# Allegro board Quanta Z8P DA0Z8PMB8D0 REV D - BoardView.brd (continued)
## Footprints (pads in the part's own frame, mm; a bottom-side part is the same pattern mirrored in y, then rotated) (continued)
C0402
  custom 0.12x0.12 smd: 1(0.39,0) 2(-0.39,0)
C0402_2
  custom 0.12x0.12 smd: 1(0.39,0) 2(-0.39,0)
C0603
  rect 0.686x0.813 smd: 1(0.6,0) 2(-0.6,0)
C0805
  rect 0.864x1.372 smd: 1(0.88,0) 2(-0.88,0)
C1206
  rect 1.219x1.626 smd: 1(1.4,0) 2(-1.4,0)
CC1808
  rect 2.159x2.286 smd: 1(-2.349,0) 2(2.349,0)
CC7343
  rect 2.413x2.819 smd: 1(-3.2,0) 2(3.2,0)
CHOKE-PCMC063T-3R3MN-SMT
  rect 1.854x3.505 smd: 1(-3.275,0) 2(3.275,0)
D-2_8X1_78
  rect 2.21x1.397 smd: 1(-0.95,0)
  rect 0.889x1.397 smd: 2(1.6,0)
D-3_8X2_5
  rect 1.6x1.905 smd: 1(-2.15,0) 2(2.15,0)
D-TO277_213-6_1X4_3
  rect 1.168x1.397 smd: 1(3.885,1.05) 2(3.885,-1.05)
  rect 4.648x3.505 smd: 3(0,0)
DFN8-2X2-5-9P-ISL6208BCRZ
  rect 0.229x0.508 smd: 1(-0.75,-0.95) 2(-0.25,-0.95) 3(0.25,-0.95) 4(0.75,-0.95) 5(0.75,0.95) 6(0.25,0.95) 7(-0.25,0.95) 8(-0.75,0.95)
  rect 1.549x0.889 smd: 9(0,0)
DFN10-3X3-5-11P-G5318
  rect 0.254x0.711 smd: 1(-1,-1.5) 2(-0.5,-1.5) 3(0,-1.5) 4(0.5,-1.5) 5(1,-1.5) 6(1,1.5) 7(0.5,1.5) 8(0,1.5) 9(-0.5,1.5) 10(-1,1.5)
  rect 2.591x1.6 smd: 11(0,0)
DFN10-4_1X2-8-11P
  rect 0.203x0.61 smd: 1(-1.8,-0.9) 2(-1,-0.9) 3(-0.2,-0.9) 4(0.6,-0.9) 5(1.4,-0.9) 6(1.8,0.9) 7(1,0.9) 8(0.2,0.9) 9(-0.6,0.9) 10(-1.4,0.9)
  rect 1.397x0.787 smd: 11(-0.4,0)
DFN-8L-3X3-65-5P-0_9H
  rect 0.508x0.356 smd: 1(1.4,-0.975) 2(1.4,-0.325) 3(1.4,0.325) 4(1.4,0.975)
  custom 0.57x0.57 smd: 5(-0.51,0)
DSM
  rect 1.016x0.508 smd: 1(-1.3,0) 2(1.321,0)
ECAP6_3X6_1-7_2
  rect 3.505x1.6 smd: 1(2.8,0) 2(-2.8,0)
ESD-1X0_6-2P
  rect 0.559x0.61 smd: 1(-0.425,0) 2(0.425,0)
ESD-3_8X1-9P
  rect 0.203x0.61 smd: 1(-1.7,-0.475) 2(-0.8,-0.475) 3(0,-0.475) 4(0.8,-0.475) 5(1.7,-0.475) 6(1.3,0.475) 7(0.4,0.475) 8(-0.4,0.475) 9(-1.3,0.475)
FBGA169-SAMSUNG-KMHOG0000M-0_5S
  round 0.254 smd: A4(-6.75,-1.75) A6(-6.75,-0.75) A9(-6.75,0.75) A11(-6.75,1.75) AA1(3.25,-3.25) AA2(3.25,-2.75) AA3(3.25,-2.25) AA4(3.25,-1.75) AA5(3.25,-1.25) AA6(3.25,-0.75) AA7(3.25,-0.25) AA8(3.25,0.25) AA9(3.25,0.75) AA10(3.25,1.25) AA11(3.25,1.75) AA12(3.25,2.25) AA13(3.25,2.75) AA14(3.25,3.25) AE1(5.25,-3.25) AE14(5.25,3.25) AG2(6.25,-2.75) AG13(6.25,2.75) AH4(6.75,-1.75) AH6(6.75,-0.75) AH9(6.75,0.75) AH11(6.75,1.75) B2(-6.25,-2.75) B13(-6.25,2.75) D1(-5.25,-3.25) D14(-5.25,3.25) H1(-3.25,-3.25) H2(-3.25,-2.75) H3(-3.25,-2.25) H4(-3.25,-1.75) H5(-3.25,-1.25) H6(-3.25,-0.75) H7(-3.25,-0.25) H8(-3.25,0.25) H9(-3.25,0.75) H10(-3.25,1.25) H11(-3.25,1.75) H12(-3.25,2.25) H13(-3.25,2.75) H14(-3.25,3.25) J1(-2.75,-3.25) J2(-2.75,-2.75) J3(-2.75,-2.25) J4(-2.75,-1.75) J5(-2.75,-1.25) J6(-2.75,-0.75) J7(-2.75,-0.25) J8(-2.75,0.25) J9(-2.75,0.75) J10(-2.75,1.25) J11(-2.75,1.75) J12(-2.75,2.25) J13(-2.75,2.75) J14(-2.75,3.25) K1(-2.25,-3.25) K2(-2.25,-2.75) K3(-2.25,-2.25) K4(-2.25,-1.75) K5(-2.25,-1.25) K6(-2.25,-0.75) K7(-2.25,-0.25) K8(-2.25,0.25) K9(-2.25,0.75) K10(-2.25,1.25) K11(-2.25,1.75) K12(-2.25,2.25) K13(-2.25,2.75) K14(-2.25,3.25) L1(-1.75,-3.25) L2(-1.75,-2.75) L3(-1.75,-2.25) L4(-1.75,-1.75) L12(-1.75,2.25) L13(-1.75,2.75) L14(-1.75,3.25) M1(-1.25,-3.25) M2(-1.25,-2.75) M3(-1.25,-2.25) M5(-1.25,-1.25) M6(-1.25,-0.75) M7(-1.25,-0.25) M8(-1.25,0.25) M9(-1.25,0.75) M10(-1.25,1.25) M12(-1.25,2.25) M13(-1.25,2.75) M14(-1.25,3.25) N1(-0.75,-3.25) N2(-0.75,-2.75) N3(-0.75,-2.25) N5(-0.75,-1.25) N10(-0.75,1.25) N12(-0.75,2.25) N13(-0.75,2.75) N14(-0.75,3.25) P1(-0.25,-3.25) P2(-0.25,-2.75) P3(-0.25,-2.25) P5(-0.25,-1.25) P10(-0.25,1.25) P12(-0.25,2.25) P13(-0.25,2.75) P14(-0.25,3.25) R1(0.25,-3.25) R2(0.25,-2.75) R3(0.25,-2.25) R5(0.25,-1.25) R10(0.25,1.25) R12(0.25,2.25) R13(0.25,2.75) R14(0.25,3.25) T1(0.75,-3.25) T2(0.75,-2.75) T3(0.75,-2.25) T5(0.75,-1.25) T10(0.75,1.25) T12(0.75,2.25) T13(0.75,2.75) T14(0.75,3.25) U1(1.25,-3.25) U2(1.25,-2.75) U3(1.25,-2.25) U5(1.25,-1.25) U6(1.25,-0.75) U7(1.25,-0.25) U8(1.25,0.25) U9(1.25,0.75) U10(1.25,1.25) U12(1.25,2.25) U13(1.25,2.75) U14(1.25,3.25) V1(1.75,-3.25) V2(1.75,-2.75) V3(1.75,-2.25) V12(1.75,2.25) V13(1.75,2.75) V14(1.75,3.25) W1(2.25,-3.25) W2(2.25,-2.75) W3(2.25,-2.25) W4(2.25,-1.75) W5(2.25,-1.25) W6(2.25,-0.75) W7(2.25,-0.25) W8(2.25,0.25) W9(2.25,0.75) W10(2.25,1.25) W11(2.25,1.75) W12(2.25,2.25) W13(2.25,2.75) W14(2.25,3.25) Y1(2.75,-3.25) Y2(2.75,-2.75) Y3(2.75,-2.25) Y4(2.75,-1.75) Y5(2.75,-1.25) Y6(2.75,-0.75) Y7(2.75,-0.25) Y8(2.75,0.25) Y9(2.75,0.75) Y10(2.75,1.25) Y11(2.75,1.75) Y12(2.75,2.25) Y13(2.75,2.75) Y14(2.75,3.25)
FILTER-MCM2012B900GBE-4P
  rect 0.762x0.406 smd: 1(-0.925,0.4) 2(0.925,0.4) 3(0.925,-0.4) 4(-0.925,-0.4)
GS12201-1011-9H-20P-L
  round 0.838 hole 0.838 unplated: (-5.8,0) (5.8,0)
  rect 0.254x1.143 smd: 1(-4.75,2.325) 2(-4.25,2.325) 3(-3.75,2.325) 4(-3.25,2.325) 5(-2.75,2.325) 6(-2.25,2.325) 7(-1.75,2.325) 8(-1.25,2.325) 9(-0.75,2.325) 10(-0.25,2.325) 11(0.25,2.325) 12(0.75,2.325) 13(1.25,2.325) 14(1.75,2.325) 15(2.25,2.325) 16(2.75,2.325) 17(3.25,2.325) 18(3.75,2.325) 19(4.25,2.325) 20(4.75,2.325)
  rect 1.295x1.397 smd: 21(-5.8,2.2) 22(5.8,2.2) 23(-5.8,-1.8) 24(5.8,-1.8)
H-C122D122N
  round 3.099 hole 3.099 unplated: (0,0)
H-C236D94P2
  round 5.994 hole 2.388: 1(0,0)
H-C236D126P2
  round 5.994 hole 3.2: 1(0,0)
H-TC252IC138BC252D138P2
  round 6.401 hole 3.505: 1(0,0)
HDMI-HMRBL-AK120C-19P
  round 0.787 hole 0.559: 1(-4.5,8.15) 2(-4,9.7) 3(-3.5,8.15) 4(-3,9.7) 5(-2.5,8.15) 6(-2,9.7) 7(-1.5,8.15) 8(-1,9.7) 9(-0.5,8.15) 10(0,9.7) 11(0.5,8.15) 12(1,9.7) 13(1.5,8.15) 14(2,9.7) 15(2.5,8.15) 16(3,9.7) 17(3.5,8.15) 18(4,9.7) 19(4.5,8.15)
  oval 1.397x2.108 hole 0.787x1.499: 20(-7.25,8.35) 21(7.25,8.35)
  oval 1.702x2.896 hole 1.092x2.311: 22(-8.75,0) 23(8.75,0)
HG-C315D165P2
  round 8.001 hole 4.191: 1(0,0)
  round 1.016 hole 0.61: 2(0,3.048) 3(2.155,2.155) 4(3.048,0) 5(2.155,-2.155) 6(0,-3.048) 7(-2.155,-2.155) 8(-3.048,0) 9(-2.155,2.155)
HG-C354D126P2
  round 8.992 hole 3.2: 1(0,0)
  round 1.016 hole 0.61: 2(0,3.048) 3(2.155,2.155) 4(3.048,0) 5(2.155,-2.155) 6(0,-3.048) 7(-2.155,-2.155) 8(-3.048,0) 9(-2.155,2.155)
HG-C354D220P2
  round 8.992 hole 5.588: 1(0,0)
  round 1.016 hole 0.61: 2(0,3.556) 3(2.514,2.514) 4(3.556,0) 5(2.514,-2.514) 6(0,-3.556) 7(-2.514,-2.514) 8(-3.556,0) 9(-2.514,2.514)
HG-EJ-AP-1
  custom 2.25x2.25 hole 3.2: 1(0,0)
  round 1.016 hole 0.61: 2(0,2.667) 3(1.886,1.886) 4(2.667,0) 5(1.886,-1.886) 6(0,-2.667) 7(-1.886,-1.886) 8(-2.667,0) 9(-1.886,1.886)
HG-TC315BC236D95P2
  round 8.001 hole 2.413: 1(0,0)
  round 1.016 hole 0.61: 2(0,2.032) 3(1.437,1.437) 4(2.032,0) 5(1.437,-1.437) 6(0,-2.032) 7(-1.437,-1.437) 8(-2.032,0) 9(-1.437,1.437)
HG-Z8P-1
  custom 2.25x2.25 hole 3.2: 1(0,0)
  round 1.016 hole 0.61: 2(0,3.048) 3(2.155,2.155) 4(3.048,0) 5(2.155,-2.155) 6(0,-3.048) 7(-2.155,-2.155) 8(-3.048,0) 9(-2.155,2.155)
JOPEN25X30_S
  custom 0.159x0.159 smd: 1(-0.368,0) 2(0.368,0)
L2_5X2-1_2H
  rect 0.889x2.108 smd: 1(-0.85,0) 2(0.85,0)
L3_2X2_5-1_55
  rect 1.245x2.007 smd: 1(-1.275,0) 2(1.275,0)
L5_1X5_2-1_6H
  rect 1.905x2.489 smd: 1(-2.047,0) 2(2.047,0)
L6_6X6_6-3_8
  rect 2.362x3.505 smd: 1(-3.025,0) 2(3.025,0)
LGA16-3X3-5
  rect 0.305x0.94 smd: 1(-1,-1.525) 2(-0.5,-1.525) 3(0,-1.525) 4(0.5,-1.525) 5(1,-1.525) 9(1,1.525) 10(0.5,1.525) 11(0,1.525) 12(-0.5,1.525) 13(-1,1.525)
  rect 0.94x0.305 smd: 6(1.525,-0.5) 7(1.525,0) 8(1.525,0.5) 14(-1.525,0.5) 15(-1.525,0) 16(-1.525,-0.5)
LQFP128-16X16-4-1_6H
  rect 0.203x1.499 smd: 1(-6.2,-7.85) 2(-5.8,-7.85) 3(-5.4,-7.85) 4(-5,-7.85) 5(-4.6,-7.85) 6(-4.2,-7.85) 7(-3.8,-7.85) 8(-3.4,-7.85) 9(-3,-7.85) 10(-2.6,-7.85) 11(-2.2,-7.85) 12(-1.8,-7.85) 13(-1.4,-7.85) 14(-1,-7.85) 15(-0.6,-7.85) 16(-0.2,-7.85) 17(0.2,-7.85) 18(0.6,-7.85) 19(1,-7.85) 20(1.4,-7.85) 21(1.8,-7.85) 22(2.2,-7.85) 23(2.6,-7.85) 24(3,-7.85) 25(3.4,-7.85) 26(3.8,-7.85) 27(4.2,-7.85) 28(4.6,-7.85) 29(5,-7.85) 30(5.4,-7.85) 31(5.8,-7.85) 32(6.2,-7.85) 65(6.2,7.85) 66(5.8,7.85) 67(5.4,7.85) 68(5,7.85) 69(4.6,7.85) 70(4.2,7.85) 71(3.8,7.85) 72(3.4,7.85) 73(3,7.85) 74(2.6,7.85) 75(2.2,7.85) 76(1.8,7.85) 77(1.4,7.85) 78(1,7.85) 79(0.6,7.85) 80(0.2,7.85) 81(-0.2,7.85) 82(-0.6,7.85) 83(-1,7.85) 84(-1.4,7.85) 85(-1.8,7.85) 86(-2.2,7.85) 87(-2.6,7.85) 88(-3,7.85) 89(-3.4,7.85) 90(-3.8,7.85) 91(-4.2,7.85) 92(-4.6,7.85) 93(-5,7.85) 94(-5.4,7.85) 95(-5.8,7.85) 96(-6.2,7.85)
  rect 1.499x0.203 smd: 33(7.85,-6.2) 34(7.85,-5.8) 35(7.85,-5.4) 36(7.85,-5) 37(7.85,-4.6) 38(7.85,-4.2) 39(7.85,-3.8) 40(7.85,-3.4) 41(7.85,-3) 42(7.85,-2.6) 43(7.85,-2.2) 44(7.85,-1.8) 45(7.85,-1.4) 46(7.85,-1) 47(7.85,-0.6) 48(7.85,-0.2) 49(7.85,0.2) 50(7.85,0.6) 51(7.85,1) 52(7.85,1.4) 53(7.85,1.8) 54(7.85,2.2) 55(7.85,2.6) 56(7.85,3) 57(7.85,3.4) 58(7.85,3.8) 59(7.85,4.2) 60(7.85,4.6) 61(7.85,5) 62(7.85,5.4) 63(7.85,5.8) 64(7.85,6.2) 97(-7.85,6.2) 98(-7.85,5.8) 99(-7.85,5.4) 100(-7.85,5) 101(-7.85,4.6) 102(-7.85,4.2) 103(-7.85,3.8) 104(-7.85,3.4) 105(-7.85,3) 106(-7.85,2.6) 107(-7.85,2.2) 108(-7.85,1.8) 109(-7.85,1.4) 110(-7.85,1) 111(-7.85,0.6) 112(-7.85,0.2) 113(-7.85,-0.2) 114(-7.85,-0.6) 115(-7.85,-1) 116(-7.85,-1.4) 117(-7.85,-1.8) 118(-7.85,-2.2) 119(-7.85,-2.6) 120(-7.85,-3) 121(-7.85,-3.4) 122(-7.85,-3.8) 123(-7.85,-4.2) 124(-7.85,-4.6) 125(-7.85,-5) 126(-7.85,-5.4) 127(-7.85,-5.8) 128(-7.85,-6.2)
ML1220-SMT
  round 0.711 hole 0.711 unplated: (0,-3.988)
  round 1.092 hole 1.092 unplated: (0,3.988)
  rect 2.997x1.499 smd: 1(-7.391,0) 2(7.391,0)
NGFF-APCI0076-P001A-75P-KE-SMT
  round 1.194 hole 1.194 unplated: (-10,0)
  round 1.702 hole 1.702 unplated: (10,0)
  rect 0.279x1.549 smd: 1(-9.25,5.275) 2(-9,-2.275) 3(-8.75,5.275) 4(-8.5,-2.275) 5(-8.25,5.275) 6(-8,-2.275) 7(-7.75,5.275) 8(-7.5,-2.275) 9(-7.25,5.275) 10(-7,-2.275) 11(-6.75,5.275) 12(-6.5,-2.275) 13(-6.25,5.275) 14(-6,-2.275) 15(-5.75,5.275) 16(-5.5,-2.275) 17(-5.25,5.275) 18(-5,-2.275) 19(-4.75,5.275) 20(-4.5,-2.275) 21(-4.25,5.275) 22(-4,-2.275) 23(-3.75,5.275) 32(-1.5,-2.275) 33(-1.25,5.275) 34(-1,-2.275) 35(-0.75,5.275) 36(-0.5,-2.275) 37(-0.25,5.275) 38(0,-2.275) 39(0.25,5.275) 40(0.5,-2.275) 41(0.75,5.275) 42(1,-2.275) 43(1.25,5.275) 44(1.5,-2.275) 45(1.75,5.275) 46(2,-2.275) 47(2.25,5.275) 48(2.5,-2.275) 49(2.75,5.275) 50(3,-2.275) 51(3.25,5.275) 52(3.5,-2.275) 53(3.75,5.275) 54(4,-2.275) 55(4.25,5.275) 56(4.5,-2.275) 57(4.75,5.275) 58(5,-2.275) 59(5.25,5.275) 60(5.5,-2.275) 61(5.75,5.275) 62(6,-2.275) 63(6.25,5.275) 64(6.5,-2.275) 65(6.75,5.275) 66(7,-2.275) 67(7.25,5.275) 68(7.5,-2.275) 69(7.75,5.275) 70(8,-2.275) 71(8.25,5.275) 72(8.5,-2.275) 73(8.75,5.275) 74(9,-2.275) 75(9.25,5.275)
  rect 1.194x2.743 smd: 76(-10.35,4.5) 77(10.35,4.5)
NGFF-NASM0-S6701-TS40-75P-KM
  round 1.194 hole 1.194 unplated: (-10,0)
  round 1.702 hole 1.702 unplated: (10,0)
  rect 0.279x1.549 smd: 1(-9.25,5.275) 2(-9,-2.275) 3(-8.75,5.275) 4(-8.5,-2.275) 5(-8.25,5.275) 6(-8,-2.275) 7(-7.75,5.275) 8(-7.5,-2.275) 9(-7.25,5.275) 10(-7,-2.275) 11(-6.75,5.275) 12(-6.5,-2.275) 13(-6.25,5.275) 14(-6,-2.275) 15(-5.75,5.275) 16(-5.5,-2.275) 17(-5.25,5.275) 18(-5,-2.275) 19(-4.75,5.275) 20(-4.5,-2.275) 21(-4.25,5.275) 22(-4,-2.275) 23(-3.75,5.275) 24(-3.5,-2.275) 25(-3.25,5.275) 26(-3,-2.275) 27(-2.75,5.275) 28(-2.5,-2.275) 29(-2.25,5.275) 30(-2,-2.275) 31(-1.75,5.275) 32(-1.5,-2.275) 33(-1.25,5.275) 34(-1,-2.275) 35(-0.75,5.275) 36(-0.5,-2.275) 37(-0.25,5.275) 38(0,-2.275) 39(0.25,5.275) 40(0.5,-2.275) 41(0.75,5.275) 42(1,-2.275) 43(1.25,5.275) 44(1.5,-2.275) 45(1.75,5.275) 46(2,-2.275) 47(2.25,5.275) 48(2.5,-2.275) 49(2.75,5.275) 50(3,-2.275) 51(3.25,5.275) 52(3.5,-2.275) 53(3.75,5.275) 54(4,-2.275) 55(4.25,5.275) 56(4.5,-2.275) 57(4.75,5.275) 58(5,-2.275) 67(7.25,5.275) 68(7.5,-2.275) 69(7.75,5.275) 70(8,-2.275) 71(8.25,5.275) 72(8.5,-2.275) 73(8.75,5.275) 74(9,-2.275) 75(9.25,5.275)
  rect 1.194x2.743 smd: 76(-10.35,4.5) 77(10.35,4.5)
O-EJ-KBL-1
  round 3.962 hole 3.962 unplated: (0,0)
POWER-3_3X3_3-65-5P-SMT
  rect 0.762x0.432 smd: 1(1.43,-0.975) 2(1.43,-0.325) 3(1.43,0.325) 4(1.43,0.975)
  custom 0.562x0.562 smd: 5(-0.725,0)
POWER-5_2X5_55-1_27-5P
  rect 0.66x0.508 smd: 1(2.755,-1.905) 2(2.755,-0.635) 3(2.755,0.635) 4(2.755,1.905)
  custom 1.15x1.15 smd: 5(0,0)
POWER-5X5-1_27-5P
  rect 1.143x0.762 smd: 1(2.875,-1.905) 2(2.875,-0.635) 3(2.875,0.635) 4(2.875,1.905)
  custom 1.14x1.14 smd: 5(0,0)
PVQFN20-3_5X3_5-5-25P
  rect 0.279x0.838 smd: 1(-1,-1.725) 2(-0.5,-1.725) 3(0,-1.725) 4(0.5,-1.725) 5(1,-1.725) 11(1,1.725) 12(0.5,1.725) 13(0,1.725) 14(-0.5,1.725) 15(-1,1.725)
  rect 0.838x0.279 smd: 6(1.725,-1) 7(1.725,-0.5) 8(1.725,0) 9(1.725,0.5) 10(1.725,1) 16(-1.725,1) 17(-1.725,0.5) 18(-1.725,0) 19(-1.725,-0.5) 20(-1.725,-1)
  rect 2.057x2.057 smd: 21(0,0)
  round 0.61 hole 0.305: 22(-0.5,-0.5) 23(0.5,-0.5) 24(0.5,0.5) 25(-0.5,0.5)
PWQFN20-4X4-5-26P-0_8H
  rect 0.279x0.991 smd: 1(-1,-1.9) 2(-0.5,-1.9) 3(0,-1.9) 4(0.5,-1.9) 5(1,-1.9) 11(1,1.9) 12(0.5,1.9) 13(0,1.9) 14(-0.5,1.9) 15(-1,1.9)
  rect 0.991x0.279 smd: 6(1.9,-1) 7(1.9,-0.5) 8(1.9,0) 9(1.9,0.5) 10(1.9,1) 16(-1.9,1) 17(-1.9,0.5) 18(-1.9,0) 19(-1.9,-0.5) 20(-1.9,-1)
  rect 2.159x2.159 smd: 21(0,0)
  round 0.61 hole 0.305: 22(-0.75,-0.75) 23(0.75,-0.75) 24(0.75,0.75) 25(-0.75,0.75) 26(0,0)
QFN10-3X3-5-16P
  rect 0.279x0.838 smd: 1(-1,-1.475) 2(-0.5,-1.475) 3(0,-1.475) 4(0.5,-1.475) 5(1,-1.475) 6(1,1.475) 7(0.5,1.475) 8(0,1.475) 9(-0.5,1.475) 10(-1,1.475)
  custom 0.413x0.413 smd: 11(0,0)
  round 0.508 hole 0.254: 12(-0.75,0.5) 13(0.75,0.5) 14(-0.75,-0.5) 15(0.75,-0.5) 16(0,0)
QFN20-3X3-45-21P
  custom 0.062x0.062 smd: 1(-0.9,-1.375) 5(0.9,-1.375) 6(1.375,-0.9) 10(1.375,0.9) 11(0.9,1.375) 15(-0.9,1.375) 16(-1.375,0.9) 20(-1.375,-0.9)
  rect 0.254x0.66 smd: 2(-0.45,-1.375) 3(0,-1.375) 4(0.45,-1.375) 12(0.45,1.375) 13(0,1.375) 14(-0.45,1.375)
  rect 0.66x0.254 smd: 7(1.375,-0.45) 8(1.375,0) 9(1.375,0.45) 17(-1.375,0.45) 18(-1.375,0) 19(-1.375,-0.45)
  rect 1.295x1.295 smd: 21(0,0)
QFN20-4X3-5-21P
  rect 0.254x0.991 smd: 1(-1.25,-1.6) 2(-0.75,-1.6) 3(-0.25,-1.6) 4(0.25,-1.6) 5(0.75,-1.6) 6(1.25,-1.6) 11(1.25,1.6) 12(0.75,1.6) 13(0.25,1.6) 14(-0.25,1.6) 15(-0.75,1.6) 16(-1.25,1.6)
  rect 0.991x0.254 smd: 7(2.1,-0.75) 8(2.1,-0.25) 9(2.1,0.25) 10(2.1,0.75) 17(-2.1,0.75) 18(-2.1,0.25) 19(-2.1,-0.25) 20(-2.1,-0.75)
  rect 2.591x1.6 smd: 21(0,0)
QFN32-5X5-5-33P-0_85H
  rect 0.305x0.991 smd: 1(-1.75,-2.6) 2(-1.25,-2.6) 3(-0.75,-2.6) 4(-0.25,-2.6) 5(0.25,-2.6) 6(0.75,-2.6) 7(1.25,-2.6) 8(1.75,-2.6) 17(1.75,2.6) 18(1.25,2.6) 19(0.75,2.6) 20(0.25,2.6) 21(-0.25,2.6) 22(-0.75,2.6) 23(-1.25,2.6) 24(-1.75,2.6)
  rect 0.991x0.305 smd: 9(2.6,-1.75) 10(2.6,-1.25) 11(2.6,-0.75) 12(2.6,-0.25) 13(2.6,0.25) 14(2.6,0.75) 15(2.6,1.25) 16(2.6,1.75) 25(-2.6,1.75) 26(-2.6,1.25) 27(-2.6,0.75) 28(-2.6,0.25) 29(-2.6,-0.25) 30(-2.6,-0.75) 31(-2.6,-1.25) 32(-2.6,-1.75)
  rect 3.505x3.505 smd: 33(0,0)
QFN32-5X5-5-37P-0_85H
  rect 0.279x0.838 smd: 1(-1.75,-2.55) 2(-1.25,-2.55) 3(-0.75,-2.55) 4(-0.25,-2.55) 5(0.25,-2.55) 6(0.75,-2.55) 7(1.25,-2.55) 8(1.75,-2.55) 17(1.75,2.55) 18(1.25,2.55) 19(0.75,2.55) 20(0.25,2.55) 21(-0.25,2.55) 22(-0.75,2.55) 23(-1.25,2.55) 24(-1.75,2.55)
  rect 0.838x0.279 smd: 9(2.55,-1.75) 10(2.55,-1.25) 11(2.55,-0.75) 12(2.55,-0.25) 13(2.55,0.25) 14(2.55,0.75) 15(2.55,1.25) 16(2.55,1.75) 25(-2.55,1.75) 26(-2.55,1.25) 27(-2.55,0.75) 28(-2.55,0.25) 29(-2.55,-0.25) 30(-2.55,-0.75) 31(-2.55,-1.25) 32(-2.55,-1.75)
  rect 3.759x3.759 smd: 33(0,0)
  round 0.508 hole 0.254: 34(-0.6,-0.6) 35(0.6,-0.6) 36(0.6,0.6) 37(-0.6,0.6)
QFN40-5X5-4-41P-ISL95859
  rect 0.203x0.61 smd: 1(-1.8,-2.4) 2(-1.4,-2.4) 3(-1,-2.4) 4(-0.6,-2.4) 5(-0.2,-2.4) 6(0.2,-2.4) 7(0.6,-2.4) 8(1,-2.4) 9(1.4,-2.4) 10(1.8,-2.4) 21(1.8,2.4) 22(1.4,2.4) 23(1,2.4) 24(0.6,2.4) 25(0.2,2.4) 26(-0.2,2.4) 27(-0.6,2.4) 28(-1,2.4) 29(-1.4,2.4) 30(-1.8,2.4)
  rect 0.61x0.203 smd: 11(2.4,-1.8) 12(2.4,-1.4) 13(2.4,-1) 14(2.4,-0.6) 15(2.4,-0.2) 16(2.4,0.2) 17(2.4,0.6) 18(2.4,1) 19(2.4,1.4) 20(2.4,1.8) 31(-2.4,1.8) 32(-2.4,1.4) 33(-2.4,1) 34(-2.4,0.6) 35(-2.4,0.2) 36(-2.4,-0.2) 37(-2.4,-0.6) 38(-2.4,-1) 39(-2.4,-1.4) 40(-2.4,-1.8)
  rect 3.505x3.505 smd: 41(0,0)
QFN48-6X6-4-49P-ALC280
  rect 0.203x0.991 smd: 1(-2.2,-3.1) 2(-1.8,-3.1) 3(-1.4,-3.1) 4(-1,-3.1) 5(-0.6,-3.1) 6(-0.2,-3.1) 7(0.2,-3.1) 8(0.6,-3.1) 9(1,-3.1) 10(1.4,-3.1) 11(1.8,-3.1) 12(2.2,-3.1) 25(2.2,3.1) 26(1.8,3.1) 27(1.4,3.1) 28(1,3.1) 29(0.6,3.1) 30(0.2,3.1) 31(-0.2,3.1) 32(-0.6,3.1) 33(-1,3.1) 34(-1.4,3.1) 35(-1.8,3.1) 36(-2.2,3.1)
  rect 0.991x0.203 smd: 13(3.1,-2.2) 14(3.1,-1.8) 15(3.1,-1.4) 16(3.1,-1) 17(3.1,-0.6) 18(3.1,-0.2) 19(3.1,0.2) 20(3.1,0.6) 21(3.1,1) 22(3.1,1.4) 23(3.1,1.8) 24(3.1,2.2) 37(-3.1,2.2) 38(-3.1,1.8) 39(-3.1,1.4) 40(-3.1,1) 41(-3.1,0.6) 42(-3.1,0.2) 43(-3.1,-0.2) 44(-3.1,-0.6) 45(-3.1,-1) 46(-3.1,-1.4) 47(-3.1,-1.8) 48(-3.1,-2.2)
  rect 4.394x4.394 smd: 49(0,0)
QFN48-6X6-4-49P-ASM1153
  rect 0.203x0.991 smd: 1(-2.2,-3.1) 2(-1.8,-3.1) 3(-1.4,-3.1) 4(-1,-3.1) 5(-0.6,-3.1) 6(-0.2,-3.1) 7(0.2,-3.1) 8(0.6,-3.1) 9(1,-3.1) 10(1.4,-3.1) 11(1.8,-3.1) 12(2.2,-3.1) 25(2.2,3.1) 26(1.8,3.1) 27(1.4,3.1) 28(1,3.1) 29(0.6,3.1) 30(0.2,3.1) 31(-0.2,3.1) 32(-0.6,3.1) 33(-1,3.1) 34(-1.4,3.1) 35(-1.8,3.1) 36(-2.2,3.1)
  rect 0.991x0.203 smd: 13(3.1,-2.2) 14(3.1,-1.8) 15(3.1,-1.4) 16(3.1,-1) 17(3.1,-0.6) 18(3.1,-0.2) 19(3.1,0.2) 20(3.1,0.6) 21(3.1,1) 22(3.1,1.4) 23(3.1,1.8) 24(3.1,2.2) 37(-3.1,2.2) 38(-3.1,1.8) 39(-3.1,1.4) 40(-3.1,1) 41(-3.1,0.6) 42(-3.1,0.2) 43(-3.1,-0.2) 44(-3.1,-0.6) 45(-3.1,-1) 46(-3.1,-1.4) 47(-3.1,-1.8) 48(-3.1,-2.2)
  rect 4.089x4.089 smd: 49(0,0)
R0402
  custom 0.12x0.12 smd: 1(0.39,0) 2(-0.39,0)
R0603
  rect 0.686x0.813 smd: 1(0.6,0) 2(-0.6,0)
R0805
  rect 0.864x1.372 smd: 1(0.88,0) 2(-0.88,0)
R1206
  rect 1.219x1.626 smd: 1(1.4,0) 2(-1.4,0)
RC3216
  rect 3.2x0.94 smd: 1(0,0.825) 2(0,-0.825)
RJ45-JM361C-HP34AA03-9H-8P-SMT
  round 1.295 hole 0.889: 1(3.57,10.1) 2(2.55,11.2) 3(1.53,10.1) 4(0.51,11.2) 5(-0.51,10.1) 6(-1.53,11.2) 7(-2.55,10.1) 8(-3.57,11.2)
  oval 1.295x2.108 hole 0.813x1.6: 9(8.4,0) 10(8.4,7.8) 11(-8.4,0) 12(-8.4,7.8)
S0402
  custom 0.125x0.125 smd: 1(0.39,0) 2(-0.39,0)
S0603
  rect 1.041x0.813 smd: 1(0.6,0) 2(-0.6,0)
S0805
  rect 1.346x1.372 smd: 1(0.88,0) 2(-0.88,0)
SC70-2_1-65-6P
  rect 1.27x0.279 smd: 1(1.02,-0.65) 2(1.02,0) 3(1.02,0.65) 4(-1.02,0.65) 5(-1.02,0) 6(-1.02,-0.65)
SC74-2_8-95-6P
  rect 1.346x0.381 smd: 1(-1.325,-0.95) 2(-1.325,0) 3(-1.325,0.95) 4(1.325,0.95) 5(1.325,0) 6(1.325,-0.95)
SDCARD-156-1001902602-11P-SMT
  round 1.219 hole 1.219 unplated: (-11.2,0)
  round 1.727 hole 1.727 unplated: (10.8,0)
  rect 0.787x1.194 smd: 1(6.905,4.6) 2(4.405,4.6) 3(1.905,4.6) 4(-0.595,4.6) 5(-3.095,4.6) 6(-5.595,4.6) 7(-8.02,4.6) 8(-9.72,4.6) 9(9.405,4.6)
  rect 1.905x1.6 smd: 10(-13.17,2.35)
  rect 1.499x1.702 smd: 11(-13.39,-4.3)
  rect 1.143x2.311 smd: 12(-13.75,-8.75) 13(13.75,-8.75)
SHORT3720
  rect 3.759x1.537 smd: 1(0,1.008) 2(0,-1.008)
SOIC8-6-1_27
  rect 0.533x1.753 smd: 1(-1.905,-2.73) 2(-0.635,-2.73) 3(0.635,-2.73) 4(1.905,-2.73) 5(1.905,2.73) 6(0.635,2.73) 7(-0.635,2.73) 8(-1.905,2.73)
SOIC8-7_9-1_27-2_16H
  rect 0.533x1.549 smd: 1(-1.905,-3.775) 2(-0.635,-3.775) 3(0.635,-3.775) 4(1.905,-3.775) 5(1.905,3.775) 6(0.635,3.775) 7(-0.635,3.775) 8(-1.905,3.775)
SON14-3X2-4-15P-SMT
  custom 0.05x0.05 smd: 1(-1.2,-1.076) 2(-0.8,-1.076) 3(-0.4,-1.076) 4(0,-1.076) 5(0.4,-1.076) 6(0.8,-1.076) 7(1.2,-1.076) 8(1.2,1.076) 9(0.8,1.076) 10(0.4,1.076) 11(0,1.076) 12(-0.4,1.076) 13(-0.8,1.076) 14(-1.2,1.076)
  rect 2.489x0.889 smd: 15(0,0)
SOP8-6-1_27-9P-G5795F11U
  rect 0.406x1.981 smd: 1(-1.905,-3.15) 2(-0.635,-3.15) 3(0.635,-3.15) 4(1.905,-3.15) 5(1.905,3.15) 6(0.635,3.15) 7(-0.635,3.15) 8(-1.905,3.15)
  rect 3.607x2.438 smd: 9(0,0)
SOT23-5
  rect 1.016x0.711 smd: 1(1.2,-0.95) 2(1.2,0) 3(1.2,0.95) 4(-1.2,0.95) 5(-1.2,-0.95)
SOT23-5-2_8-95-5P-G708
  rect 1.194x0.533 smd: 1(1.5,-0.95) 2(1.5,0) 3(1.5,0.95) 4(-1.5,0.95) 5(-1.5,-0.95)
SOT23-6-2_8-95-6P
  rect 1.194x0.508 smd: 1(1.5,-0.95) 2(1.5,0) 3(1.5,0.95) 4(-1.5,0.95) 5(-1.5,0) 6(-1.5,-0.95)
SOT23-6-2_8-95-6P-G5126TB1U
  rect 1.194x0.508 smd: 1(1.5,-0.95) 2(1.5,0) 3(1.5,0.95) 4(-1.5,0.95) 5(-1.5,0) 6(-1.5,-0.95)
SOT23_213-3_3-2
  rect 1.27x1.016 smd: 1(1.016,1.016) 2(1.016,-1.016) 3(-1.016,0)
SOT363-2_1-65-6P
  rect 0.889x0.356 smd: 1(0.8,-0.65) 2(0.8,0) 3(0.8,0.65) 4(-0.8,0.65) 5(-0.8,0) 6(-0.8,-0.65)
SPAD-C177NP
  round 4.496 smd: 1(0,0)
SPAD-C236NP
  round 5.994 smd: 1(0,0)
SPAD-C315NP
  round 8.001 smd: 1(0,0)
SW-DS-A40E-4P-SMT
  round 1.219 hole 1.219 unplated: (0,-1.5)
  oval 1.016x1.092 hole 1.016x1.092 unplated: (0,1)
  rect 0.787x1.194 smd: 1(-2.15,-1.2) 2(-2.15,1.2) 3(2.15,-1.2) 4(2.15,1.2)
SW-TME-532-V-6P
  rect 1.803x1.092 smd: 1(-3.1,1.85) 2(3.1,1.85) 3(-3.1,-1.85) 4(3.1,-1.85)
  rect 0.991x0.61 smd: 5(0,2.5) 6(0,-2.5)
TP2050
  round 0.508 smd: 1(0,0)
TRF-15_1X10-1-25P
  rect 0.61x1.346 smd: 1(-5.5,-4.675) 2(-4.5,-4.675) 3(-3.5,-4.675) 4(-2.5,-4.675) 5(-1.5,-4.675) 6(-0.5,-4.675) 7(0.5,-4.675) 8(1.5,-4.675) 9(2.5,-4.675) 10(3.5,-4.675) 11(4.5,-4.675) 12(5.5,-4.675) 13(5.5,4.675) 14(4.5,4.675) 15(3.5,4.675) 16(2.5,4.675) 17(1.5,4.675) 18(0.5,4.675) 19(-0.5,4.675) 20(-1.5,4.675) 21(-2.5,4.675) 22(-3.5,4.675) 23(-4.5,4.675) 24(-5.5,4.675)
  rect 0.787x0.787 smd: 25(-6.75,0)
TSOT23-2_8-95-5P-G916-475TOUF
  rect 1.194x0.533 smd: 1(1.5,-0.95) 2(1.5,0) 3(1.5,0.95) 4(-1.5,0.95) 5(-1.5,-0.95)
UB3-53930-00902-V01-9P
  round 1.092 hole 0.787: 1(3.5,9.47) 2(1,9.47) 3(-1,9.47) 4(-3.5,9.47) 5(-4,7.97) 6(-2,7.97) 7(0,7.97) 8(2,7.97) 9(4,7.97)
  oval 1.397x3.2 hole 0.787x2.591: 10(7.15,8.6) 11(-7.15,8.6)
  oval 1.397x2.489 hole 0.787x1.905: 12(-7.85,0) 13(7.85,0)
UB31-AUSB0181-P101A-24P
  round 0.813 hole 0.813 unplated: (-3.6,0)
  oval 0.813x0.762 hole 0.813x0.762 unplated: (3.6,0)
  oval 0.762x1.346 hole 0.508x1.092: 1(-4.13,-1.25) 2(4.13,-1.25)
  oval 0.762x1.651 hole 0.508x1.397: 3(-4.49,-4.1) 4(4.49,-4.1)
  rect 0.254x0.991 smd: A1(-2.75,0.61) A2(-2.25,0.61) A3(-1.75,0.61) A4(-1.25,0.61) A5(-0.75,0.61) A6(-0.25,0.61) A7(0.25,0.61) A8(0.75,0.61) A9(1.25,0.61) A10(1.75,0.61) A11(2.25,0.61) A12(2.75,0.61)
  oval 0.61x0.787 hole 0.457: B1(2.8,-0.65) B2(2.4,-1.35) B3(1.6,-1.35) B4(1.2,-0.65) B5(0.8,-1.35) B6(0.4,-0.65) B7(-0.4,-0.65) B8(-0.8,-1.35) B9(-1.2,-0.65) B10(-1.6,-1.35) B11(-2.4,-1.35) B12(-2.8,-0.65)
UDFN10-2_5X1-5-9P
  rect 0.203x0.686 smd: 1(-1,-0.437) 2(-0.5,-0.437) 4(0.5,-0.437) 5(1,-0.437) 6(1,0.437) 7(0.5,0.437) 9(-0.5,0.437) 10(-1,0.437)
  rect 0.406x1.549 smd: 3(0,0)
UMT_213-3-1_3
  rect 1.016x0.762 smd: 1(0.991,0.66) 2(0.991,-0.66) 3(-0.991,0)
unnamed
  round 1.016 smd: 1(0,0)
WQFN20-3X3-4-21P
  rect 0.203x0.991 smd: 1(-0.8,-1.6) 2(-0.4,-1.6) 3(0,-1.6) 4(0.4,-1.6) 5(0.8,-1.6) 11(0.8,1.6) 12(0.4,1.6) 13(0,1.6) 14(-0.4,1.6) 15(-0.8,1.6)
  rect 0.991x0.203 smd: 6(1.6,-0.8) 7(1.6,-0.4) 8(1.6,0) 9(1.6,0.4) 10(1.6,0.8) 16(-1.6,0.8) 17(-1.6,0.4) 18(-1.6,0) 19(-1.6,-0.4) 20(-1.6,-0.8)
  rect 1.702x1.702 smd: 21(0,0)
XTL-3_2X1_5-2_5-0_8H
  rect 0.991x1.803 smd: 1(-1.25,0) 2(1.25,0)
XTL-3_2X2_5-2_2X1_7-0_8H
  rect 1.397x1.194 smd: 1(-1.1,-0.85) 2(1.1,-0.85) 3(1.1,0.85) 4(-1.1,0.85)
XTL-3_2X2_5-2_2X1_7-4P-1H
  rect 1.397x1.194 smd: 1(-1.1,-0.85) 2(1.1,-0.85) 3(1.1,0.85) 4(-1.1,0.85)

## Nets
1.8V_LDO: C393.2 R448.1 U30.5(VOUT)
1.35VSUS_VIN: JP9.1 PC191.1 PC192.1 PC193.1 PC196.1 PQ18.5(D) PR194.1
3VPCU_VIN: JP1.1 PC63.1 PC64.1 PC65.1 PC68.1 PC69.1 PU5.2(IN#1) PU5.3(IN#2) PU5.4(IN#3) PU5.5(IN#4)
5VPCU_VIN: JP7.1 PC151.1 PC152.1 PC154.1 PC155.1 PC157.1 PU11.2(IN#1) PU11.3(IN#2) PU11.4(IN#3) PU11.5(IN#4)
+1.2V_ASM: C387.2 C388.2 C392.2 C404.2 C406.2 C421.1 C422.2 L10.1 U32.7(VDD#1) U32.13(VDDU#1) U32.24(VDDU#2) U32.28(VDDS) U32.36(VDD#2) U32.46(VDD#3)
+1.5V: C257.1 C261.1 C397.2 L8.2 PR181.2 Q32.2(G) U15.9(DVDD-IO)
+1.05V: C313.2 JP5.2 PR27.1 PR122.1 R323.1 R324.1 R373.1 R378.1 R383.1
+1.5VA: C220.1 C401.1 L8.1 U15.40(AVDD2)
+1.8V: PQ4.1(S) PR39.1 Q10.2(G) Q10.5(G) R4.1 R63.1 R103.1 R112.1 R325.1
+1.8V_EMMC: C316.2 C317.1 C319.2 C321.2 C331.1 R325.2 U2.AA3(VCCQ_5) U2.AA5(VCCQ_2) U2.K6(VCCQ_1) U2.W4(VCCQ_3) U2.Y4(VCCQ_4)
+1.8V_S5: JP11.2 PQ4.3(D) PR50.2 Q15.2(G) Q15.5(G) Q21.2(G) Q21.5(G) R16.2 R17.2 R18.2 R19.1 R20.1 R23.2 R25.1 R26.1 R27.2 R28.2 R86.1 R90.1 R92.1 R93.1 R290.2 R291.2 R292.2 R293.2 R294.2 R295.2 R296.2 R303.2 R304.2 R305.2 R306.2 R307.2 R308.1 R309.2 R310.2 R311.2 R312.2 R314.2 R315.2 R316.2 R317.2 R318.2 R319.2 R320.2 R321.1 R327.2 R328.2 R330.2 R356.1 R360.1 R363.2 R366.2 R377.2 R381.1 R384.2 R390.1 R391.1 R392.1 R397.1 R398.1 R418.1 R492.2 U4.1(VCCA) U22.1(VCCA) U29.1(VCCA)
+1.24V_S5: JP12.2 R387.1 R388.1 R394.1 R395.1 R396.1
+1.35VSUS: C84.2 C88.2 C89.2 C94.2 C95.2 C96.1 C98.2 C99.2 C100.2 C104.1 C120.2 C121.1 C132.2 C133.2 C134.2 C136.1 C143.1 C148.1 C150.2 C151.2 C153.1 C157.1 C158.2 C160.2 C162.2 C164.2 C166.1 C168.1 C171.1 C175.1 C354.1 C355.1 C356.1 C357.1 C358.1 C360.1 C361.1 C362.2 C363.1 C364.1 C365.1 C366.1 C367.1 C368.1 C369.1 C371.2 C372.1 C373.1 C374.1 C375.1 C376.1 C377.1 C378.1 C379.1 JP10.2 PC202.1 PU15.19(VLDOIN) R105.1 R106.1 R144.2 R145.2 R148.2 R152.1 R160.1 R166.2 U8.A1(VDDQ#A1) U8.A8(VDDQ#A8) U8.B2(VDD#B2) U8.C1(VDDQ#C1) U8.C9(VDDQ#C9) U8.D2(VDDQ#D2) U8.D9(VDD#D9) U8.E9(VDDQ#E9) U8.F1(VDDQ#F1) U8.G7(VDD#G7) U8.H2(VDDQ#H2) U8.H9(VDDQ#H9) U8.K2(VDD#K2) U8.K8(VDD#K8) U8.N1(VDD#N1) U8.N9(VDD#N9) U8.R1(VDD#R1) U8.R9(VDD#R9) U9.A1(VDDQ#A1) U9.A8(VDDQ#A8) U9.B2(VDD#B2) U9.C1(VDDQ#C1) U9.C9(VDDQ#C9) U9.D2(VDDQ#D2) U9.D9(VDD#D9) U9.E9(VDDQ#E9) U9.F1(VDDQ#F1) U9.G7(VDD#G7) U9.H2(VDDQ#H2) U9.H9(VDDQ#H9) U9.K2(VDD#K2) U9.K8(VDD#K8) U9.N1(VDD#N1) U9.N9(VDD#N9) U9.R1(VDD#R1) U9.R9(VDD#R9) U10.A1(VDDQ#A1) U10.A8(VDDQ#A8) U10.B2(VDD#B2) U10.C1(VDDQ#C1) U10.C9(VDDQ#C9) U10.D2(VDDQ#D2) U10.D9(VDD#D9) U10.E9(VDDQ#E9) U10.F1(VDDQ#F1) U10.G7(VDD#G7) U10.H2(VDDQ#H2) U10.H9(VDDQ#H9) U10.K2(VDD#K2) U10.K8(VDD#K8) U10.N1(VDD#N1) U10.N9(VDD#N9) U10.R1(VDD#R1) U10.R9(VDD#R9) U11.A1(VDDQ#A1) U11.A8(VDDQ#A8) U11.B2(VDD#B2) U11.C1(VDDQ#C1) U11.C9(VDDQ#C9) U11.D2(VDDQ#D2) U11.D9(VDD#D9) U11.E9(VDDQ#E9) U11.F1(VDDQ#F1) U11.G7(VDD#G7) U11.H2(VDDQ#H2) U11.H9(VDDQ#H9) U11.K2(VDD#K2) U11.K8(VDD#K8) U11.N1(VDD#N1) U11.N9(VDD#N9) U11.R1(VDD#R1) U11.R9(VDD#R9) U21.AN18(VDDQ_1) U21.AN20(VDDQ_2) U21.AN22(VDDQ_3) U21.AN23(VDDQ_4) U21.AN41(VDDQ_5) U21.AN42(VDDQ_6) U21.AN44(VDDQ_7) U21.AN46(VDDQ_8) U21.AR17(VDDQ_9) U21.AR47(VDDQ_10) U21.AT13(VDDQ_11) U21.AT17(VDDQ_12) U21.AT47(VDDQ_13) U21.AT51(VDDQ_14) U21.AV14(VDDQ_15) U21.AV50(VDDQ_16) U24.A1(VDDQ#A1) U24.A8(VDDQ#A8) U24.B2(VDD#B2) U24.C1(VDDQ#C1) U24.C9(VDDQ#C9) U24.D2(VDDQ#D2) U24.D9(VDD#D9) U24.E9(VDDQ#E9) U24.F1(VDDQ#F1) U24.G7(VDD#G7) U24.H2(VDDQ#H2) U24.H9(VDDQ#H9) U24.K2(VDD#K2) U24.K8(VDD#K8) U24.N1(VDD#N1) U24.N9(VDD#N9) U24.R1(VDD#R1) U24.R9(VDD#R9) U25.A1(VDDQ#A1) U25.A8(VDDQ#A8) U25.B2(VDD#B2) U25.C1(VDDQ#C1) U25.C9(VDDQ#C9) U25.D2(VDDQ#D2) U25.D9(VDD#D9) U25.E9(VDDQ#E9) U25.F1(VDDQ#F1) U25.G7(VDD#G7) U25.H2(VDDQ#H2) U25.H9(VDDQ#H9) U25.K2(VDD#K2) U25.K8(VDD#K8) U25.N1(VDD#N1) U25.N9(VDD#N9) U25.R1(VDD#R1) U25.R9(VDD#R9) U26.A1(VDDQ#A1) U26.A8(VDDQ#A8) U26.B2(VDD#B2) U26.C1(VDDQ#C1) U26.C9(VDDQ#C9) U26.D2(VDDQ#D2) U26.D9(VDD#D9) U26.E9(VDDQ#E9) U26.F1(VDDQ#F1) U26.G7(VDD#G7) U26.H2(VDDQ#H2) U26.H9(VDDQ#H9) U26.K2(VDD#K2) U26.K8(VDD#K8) U26.N1(VDD#N1) U26.N9(VDD#N9) U26.R1(VDD#R1) U26.R9(VDD#R9) U27.A1(VDDQ#A1) U27.A8(VDDQ#A8) U27.B2(VDD#B2) U27.C1(VDDQ#C1) U27.C9(VDDQ#C9) U27.D2(VDDQ#D2) U27.D9(VDD#D9) U27.E9(VDDQ#E9) U27.F1(VDDQ#F1) U27.G7(VDD#G7) U27.H2(VDDQ#H2) U27.H9(VDDQ#H9) U27.K2(VDD#K2) U27.K8(VDD#K8) U27.N1(VDD#N1) U27.N9(VDD#N9) U27.R1(VDD#R1) U27.R9(VDD#R9)
+1.35VSUS_SRC: JP10.1 PC194.1 PC198.1 PC203.1 PC205.1 PC208.1 PC211.1 PC212.1 PL9.2 PR190.2
+3V: C105.2 C106.2 C109.2 C126.2 C127.2 C128.2 C129.2 C130.2 C131.2 C137.2 C277.1 C280.1 C315.1 C352.1 PC135.1 PC139.1 PR42.1 PR129.1 PR131.1 PR144.1 PR186.1 PR197.1 PU7.8(OUT2#1) PU7.9(OUT2#2) Q5.2(G) Q13.2(G) Q29.2(G) Q29.5(G) R3.1 R7.2 R21.2 R22.2 R38.2 R45.2 R66.1 R118.2 R119.2 R163.2 R176.2 R177.2 R222.1 R223.1 R224.1 R231.1 R234.1 R238.2 R252.2 R256.2 R276.1 R279.2 R289.2 R297.2 R298.2 R299.2 R300.2 R332.2 R336.2 R337.2 R353.1 R393.1 R416.1 R443.2 R487.2 R488.2 U6.1(VDD#1) U6.18(VDD#2) U6.22(DDC_EN) U17.1(VDD_IO) U17.8(CS) U17.14(VDD) U19.4(IN#1) U19.5(IN#2) U23.4(+VS)
+3V_ASM: C385.1 C389.2 C390.1 C391.2 C398.2 C400.1 C413.2 C414.2 C419.2 R472.1 U31.3(W\P\) U31.7(H\O\L\D\) U31.8(VCC) U32.1(VCCIN) U32.4(VCC#1) U32.12(VCCO) U32.14(VCCU#1) U32.18(VCCU#2) U32.27(VCCTXL) U32.34(VCCS) U32.39(VCC#2)
+3V_CR: R234.2 U13.12(DVDD33_CR)
+3V_EC: C251.1 R248.2 U16.11(VCC)
+3V_EMMC: C320.1 C322.2 C327.2 C328.1 C329.2 R353.2 U2.M6(VCC_3) U2.N5(VCC_4) U2.T10(VCC_1) U2.U9(VCC_2)
+3V_LDO_EC: D24.1(CATHODE) R202.2 R206.2 R211.2 R212.2 R213.2 R450.2 R459.1 R462.2
+3V_M2: C337.2 C338.2 C339.2 C345.2 C346.2 CN5.2 CN5.4 CN5.12 CN5.14 CN5.16 CN5.18 CN5.70 CN5.72 CN5.74 R393.2 R484.1 R490.2 U4.6(VCCB)
+3V_RTC: C45.2 D26.3(COMMON ANODE) R62.2 R245.1 R246.1 R446.2 R455.2 U21.AA44(VCCRTC_3P3V)
+3V_RTC_1: D26.1(CATHODE1) R463.2
+3V_S5: C266.1 PC111.1 PC115.1 PR149.1 PR160.1 PU7.13(VOUT1#1) PU7.14(VOUT1#2) R50.1 R51.1 R56.1 R65.1 R67.2 R69.1 R71.1 R76.1 R77.1 R79.1 R80.1 R81.1 R82.1 R84.1 R85.2 R209.2 R236.2 R248.1 R258.2 R259.2 R261.2 R263.1 R264.2 R267.2 R268.2 R365.2 R368.2 R389.2 U22.6(VCCB)
+3VPCU: CN17.7 D26.2(CATHODE2) JP4.2 JP6.1 PC42.1 PC116.1 PC136.1 PR41.1 PR56.2 PR60.2 PR62.2 PR63.2 PR79.2 PR80.2 PR81.2 PR88.1 PR150.1 PR180.1 PU7.1(VIN1#1) PU7.2(VIN1#2) PU7.6(VIN2#1) PU7.7(VIN2#2) R11.2 R151.2 R454.2 U15.20(VD33 STB)
+3VPCU_EC: C205.1 C209.1 C408.1 C410.1 C415.1 C440.1 L4.2 L12.1 R459.2 U16.26(VSTBY#1) U16.50(VSTBY#2) U16.92(VSTBY#3) U16.114(VSTBY#4) U16.121(VSTBY#5)
+3VPCU_ECPLL: C208.1 L4.1 U16.127(VSTBY(PLL))
+3VPCU_SRC: JP4.1 PC102.1 PC107.1 PC112.1 PC121.1 PC122.1 PC123.1 PL3.2 PR125.1
+5V: C265.2 L9.1 L11.1 PC180.1 PC182.1 PR43.1 PU13.8(OUT2#1) PU13.9(OUT2#2) Q22.1(S) R229.1 R230.2 R260.2 R266.1 R277.1 R461.2 U5.3(IN)
+5V_FAN1: CN10.1 R230.1
+5V_KB: C273.2 C279.2 CN18.2 CN18.4 Q22.3(D)
+5V_ODD: C405.2 C418.2 C429.1 C430.2 C438.2 C439.2 CN16.9 CN16.10 CN16.11 CN16.12 CN16.13 CN16.14 CN16.15 R456.2 R461.1 U32.11(VBUS_LDO)
+5V_PVDD: C213.1 C214.1 C411.1 C412.1 L9.2 U15.41(PVDD1) U15.46(PVDD2)
+5V_S5: C52.2 C53.2 C135.1 C278.1 C394.1 ESD1.5(VDD) PC179.1 PC181.1 PR1.1 PR2.1 PR64.2 PR65.2 PR117.1 PR132.2 PR204.1 PU13.13(VOUT1#1) PU13.14(VOUT1#2) R96.1 R468.1 R474.1 U3.2(IN1#1) U3.3(IN1#2) U3.4(IN2) U3.5(AUX) U7.5(IN) U18.5(IN)
+5VA: C259.1 C428.1 L11.2 U15.26(AVDD1)
+5VPCU: JP8.2 PC177.1 PC178.1 PR137.2 PR173.2 PR179.2 PU13.1(VIN1#1) PU13.2(VIN1#2) PU13.6(VIN2#1) PU13.7(VIN2#2)
+5VPCU_SRC: JP8.1 PC168.1 PC169.1 PC170.1 PC171.1 PC172.1 PC173.1 PL8.2 PR171.1
+12V_PANEL: PC127.2 PC138.2 PC145.2 PC146.2 PD1.1(CATHODE) PR9.2 PR210.1 R6.1
+A3VPCU: C267.1 L12.2 U16.74(AVCC)
+VCC_1.05V_INT: R383.2 U21.P16(VCC_1P05V_FUSE) U21.T13(VCC_1P05V_FHV0) U21.T15(VCC_1P05V_FHV1)
+VCC_1.05V_IO: C17.1 C19.1 C20.1 C21.1 C25.1 C26.1 C30.1 C32.2 C35.2 C40.2 C44.1 R373.2 R378.2 U21.AA22(VCC_1P05V_IO_1) U21.AA23(VCC_1P05V_3PHASEIO) U21.AA25(VCC_1P05V_1) U21.AC23(VCC_1P05V_IO_2) U21.AC25(VCC_1P05V_2) U21.AE25(VCC_1P05V_3) U21.U20(VCC_1P05V_12) U21.U22(VCC_1P05V_4) U21.U23(VCC_1P05V_5) U21.U25(VCC_1P05V_11) U21.V18(VCC_1P05V_IO_3) U21.V22(VCC_1P05V_6) U21.V23(VCC_1P05V_7) U21.V25(VCC_1P05V_8) U21.Y18(VCC_1P05V_IO_4) U21.Y20(VCC_1P05V_IO_5) U21.Y23(VCC_1P05V_9) U21.Y25(VCC_1P05V_10)
+VCC_1.8V: C59.1 C61.1 C62.1 C63.1 C91.2 R86.2 U21.AA46(VCC_1P8V_A_1) U21.AC42(VCC_1P8V_A_5) U21.AC44(VCC_1P8V_A_6) U21.AC46(VCC_1P8V_A_2) U21.AE42(VCC_1P8V_A_4) U21.AE44(VCC_1P8V_A_3) U21.AE46(VCC_1P8V_A_7) U21.AG25(VCC_1P8V_A_8)
+VCC_1.24V_AUD_ISH_PLL: C72.1 C74.1 C348.2 R394.2 U21.AJ20(VCC_1P24V_1P35V_A_PLL_1) U21.AJ22(VCC_1P24V_1P35V_A_PLL_2) U21.AK22(VCC_1P24V_1P35V_A_AUD_ISH)
+VCC_1.24V_DSI_CSI: C57.1 C60.1 C69.2 R388.2 U21.AA18(VDD2_1P24_DSI_CSI#1) U21.AA20(VDD2_1P24_DSI_CSI#2)
+VCC_1.24V_GLM: C80.1 C82.1 C83.1 C86.1 C351.2 R396.2 U21.AK20(VCC_1P24V_1P35V_A_GLML2) U21.AM20(VCC_1P24V_1P35V_A_GLML2LDO_1) U21.AM28(VCC_1P24V_1P35V_A_GLML2LDO_2) U21.AM37(VCC_1P24V_1P35V_A_GLML2LDO_3)
+VCC_1.24V_MPHY: C49.1 C56.1 C68.2 C71.1 R387.2 U21.AE18(VCC_1P24V_1P35V_A_MPHY_1) U21.AE20(VCC_1P24V_1P35V_A_MPHY_2) U21.AE22(VCC_1P24V_1P35V_A_MPHY_3) U21.AG22(VCC_1P24V_1P35V_A_MPHY_4)
+VCC_1.24V_USB2: C67.1 R395.2 U21.AG20(VCC_1P24V_1P35V_A_USB2)
+VCC_3.3V: C37.1 C38.1 C48.1 C77.1 C92.2 R84.2 U21.AA42(VCC_3P3V_A_2) U21.AC41(VCC_3P3V_A_1) U21.AJ25(VCC_3P3V_A_USB_1) U21.AK25(VCC_3P3V_A_USB_2) U21.V44(VCC_3P3V_A_4) U21.V46(VCC_3P3V_A_5) U21.Y44(VCC_3P3V_A_3)
+VCC_VCCGI: C3.1 C4.2 C6.2 C7.2 C8.2 C11.1 C12.1 C13.1 C14.1 C15.1 C16.1 C23.1 C24.1 C27.1 C29.1 C31.1 C33.2 C39.1 C41.2 C46.2 C66.2 C81.2 C296.2 C300.2 PC20.1 PC21.1 PC22.1 PC24.1 PC25.1 PC30.1 PC99.1 PC103.1 PC105.1 PC108.1 PC109.1 PC113.1 PC114.1 PC118.1 PC126.1 PC128.1 PC129.1 PC130.1 PC131.1 PC132.1 PC133.1 PC134.1 PL4.2 PR30.1 PR126.2 U21.AA28(VCC_VCGI_32) U21.AA30(VCC_VCGI_33) U21.AA32(VCC_VCGI_34) U21.AA36(VCC_VCGI_1) U21.AA37(VCC_VCGI_2) U21.AA39(VCC_VCGI_3) U21.AC28(VCC_VCGI_35) U21.AC30(VCC_VCGI_36) U21.AC32(VCC_VCGI_37) U21.AC36(VCC_VCGI_4) U21.AC37(VCC_VCGI_5) U21.AE28(VCC_VCGI_38) U21.AE30(VCC_VCGI_39) U21.AE32(VCC_VCGI_40) U21.AE36(VCC_VCGI_6) U21.AE37(VCC_VCGI_7) U21.AG28(VCC_VCGI_41) U21.AG30(VCC_VCGI_42) U21.AG32(VCC_VCGI_43) U21.AG36(VCC_VCGI_8) U21.AJ28(VCC_VCGI_44) U21.AJ30(VCC_VCGI_45) U21.AJ32(VCC_VCGI_46) U21.AK28(VCC_VCGI_47) U21.AK30(VCC_VCGI_48) U21.AK32(VCC_VCGI_49) U21.AK34(VCC_VCGI_50) U21.AM30(VCC_VCGI_51) U21.E29(VCC_VCGI_52) U21.E35(VCC_VCGI_53) U21.E37(VCC_VCGI_54) U21.E43(VCC_VCGI_9) U21.E45(VCC_VCGI_10) U21.E48(VCC_VCGI_11) U21.E50(VCC_VCGI_12) U21.F29(VCC_VCGI_55) U21.R45(VCC_VCGI_13) U21.R47(VCC_VCGI_14) U21.U28(VCC_VCGI_56) U21.U30(VCC_VCGI_57) U21.U32(VCC_VCGI_58) U21.U36(VCC_VCGI_15) U21.U37(VCC_VCGI_16) U21.U39(VCC_VCGI_17) U21.U41(VCC_VCGI_18) U21.U42(VCC_VCGI_19) U21.U44(VCC_VCGI_20) U21.U46(VCC_VCGI_21) U21.U47(VCC_VCGI_22) U21.U48(VCC_VCGI_23) U21.V28(VCC_VCGI_59) U21.V30(VCC_VCGI_60) U21.V32(VCC_VCGI_61) U21.V36(VCC_VCGI_24) U21.V37(VCC_VCGI_25) U21.V39(VCC_VCGI_26) U21.V41(VCC_VCGI_27) U21.Y28(VCC_VCGI_62) U21.Y30(VCC_VCGI_63) U21.Y32(VCC_VCGI_64) U21.Y36(VCC_VCGI_28) U21.Y37(VCC_VCGI_29) U21.Y39(VCC_VCGI_30) U21.Y41(VCC_VCGI_31)
+VDDI_EMMC: C330.1 U2.K2(VDDI)
+VDDQ: PC39.1 PR48.1
+VDDQ_VTT: PC197.1 PU15.2(VTTSNS) PU15.20(VTT) R178.1 R179.1 R180.1 R181.1 R182.1 R183.1 R184.1 R185.1 R186.1 R187.1 R188.1 R189.1 R190.1 R191.1 R192.1 R193.1 R194.1 R195.1 R196.1 R197.1 R198.1 R199.1 R200.1 R201.1 R419.1 R420.1 R421.1 R422.1 R423.1 R424.1 R425.1 R426.1 R427.1 R428.1 R429.1 R430.1 R431.1 R432.1 R433.1 R434.1 R435.1 R436.1 R437.1 R438.1 R439.1 R440.1 R441.1 R442.1
+VIN: JP1.2 JP2.2 JP3.2 JP7.2 JP9.2 PC48.2 PC49.2 PC80.1 PC165.1 PC199.1 PC206.1 PC209.1 PQ17.1(S1) PQ17.2(S2) PQ17.3(S3) PQ20.5(D) PR35.1 PR36.1 PR44.2 PR45.2 PR49.1 PR93.1 PR114.2 PR158.1 PR209.1 R5.1
